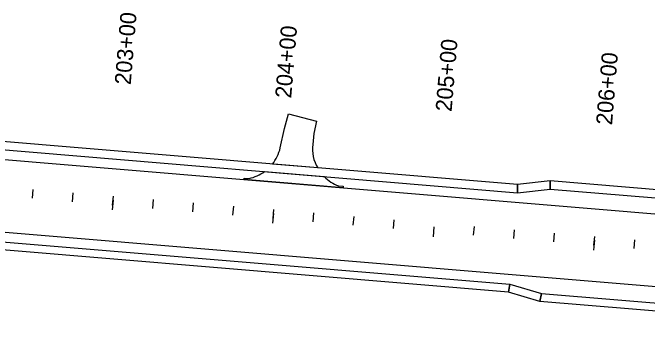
# Model space of a CAD drawing. Extents: x 20499216 to 20505321, y 7953487 to 7960535.
# Drawn here: x 20503938.3 to 20504332.5, y 7953624.2 to 7953822.6 of the extents above; entities that cross this region are included whole.
import ezdxf

# ---------------------------------------------------------------- set-up
doc = ezdxf.new("R2010")
doc.units = 0
for name, color, linetype in [('EXT_CU', 7, 'Continuous'), ('EXT_RR', 7, 'Continuous'), ('NamedBoundary', 7, 'Continuous'), ('Safety', 7, 'Continuous')]:
    doc.layers.add(name, color=color, linetype=linetype)

msp = doc.modelspace()

# ---------------------------------------------------------------- linework, layer by layer
at = {"layer": 'EXT_CU'}
for points in [[(20503897.02, 7953745.48), (20503896.61, 7953740.5), (20504251.88, 7953710.85), (20504251.8, 7953715.88)], [(20504251.88, 7953710.85), (20504272.15, 7953713.17), (20504272.08, 7953718.2), (20504251.8, 7953715.88)], [(20504246.23, 7953649.11), (20503815.16, 7953685.08), (20503815.08, 7953690.11), (20504247.14, 7953654.05)], [(20504265.83, 7953643.46), (20504246.23, 7953649.11), (20504247.14, 7953654.05), (20504266.74, 7953648.4)], [(20504266.74, 7953648.4), (20504496.4, 7953629.24), (20504496.05, 7953624.25), (20504265.83, 7953643.46)]]:
    msp.add_lwpolyline(points, close=True, dxfattribs=at)
msp.add_lwpolyline([(20504432.72, 7953704.8), (20504368.14, 7953710.18), (20504368.14, 7953710.18), (20504272.08, 7953718.2), (20504272.15, 7953713.17), (20504367.73, 7953705.2), (20504367.73, 7953705.2), (20504432.3, 7953699.81)], dxfattribs=at)
at = {"layer": 'EXT_RR'}
for p, q in [((20503950.55, 7953707.4), (20503951, 7953712.84)), ((20503975.46, 7953705.32), (20503975.91, 7953710.76)), ((20504000.63, 7953706.29), (20504000.12, 7953700.19)), ((20504025.29, 7953701.16), (20504025.74, 7953706.6)), ((20504050.2, 7953699.08), (20504050.65, 7953704.52)), ((20504075.11, 7953697), (20504075.57, 7953702.44)), ((20504100.28, 7953697.97), (20504099.77, 7953691.88)), ((20504124.94, 7953692.85), (20504125.39, 7953698.29)), ((20504149.85, 7953690.77), (20504150.31, 7953696.21)), ((20504174.77, 7953688.69), (20504175.22, 7953694.13)), ((20504199.94, 7953689.66), (20504199.43, 7953683.56)), ((20504224.59, 7953684.53), (20504225.05, 7953689.97)), ((20504249.51, 7953682.45), (20504249.96, 7953687.89)), ((20504274.42, 7953680.37), (20504274.88, 7953685.81)), ((20504299.59, 7953681.34), (20504299.08, 7953675.24)), ((20504324.25, 7953676.21), (20504324.7, 7953681.66))]:
    msp.add_line(p, q, dxfattribs=at)
at = {"layer": 'NamedBoundary'}
for p, q in [((20504127.84, 7953726.22), (20504099.61, 7953728.58)), ((20504094.74, 7953723.96), (20504131.87, 7953720.87))]:
    msp.add_line(p, q, dxfattribs=at)
for points in [[(20503281.84, 7953797.82), (20503630.7, 7953768.71), (20503809.08, 7953741.78), (20504366.9, 7953695.23), (20504431.47, 7953689.85)], [(20504104.51, 7953738.74), (20504107.23, 7953750.76), (20504109.62, 7953759.85), (20504126.95, 7953755.29), (20504125.41, 7953747.59), (20504124.76, 7953740.85)], [(20504427.73, 7953645), (20504246.09, 7953660.16), (20503289.01, 7953740.03), (20503289.01, 7953740.03)], [(20504140.67, 7953715.11), (20504143.66, 7953714.87), (20504143.58, 7953713.87), (20504082.04, 7953719), (20504082.12, 7953720), (20504085.11, 7953719.75)]]:
    msp.add_lwpolyline(points, dxfattribs=at)
for centre, radius, start, end in [((20504145.85, 7953737.65), 21.33, 171.3771, 212.4055), ((20504078.51, 7953745.03), 26.76, 322.0441, 346.3982), ((20504080.13, 7953744.25), 25, 281.4903, 305.7659), ((20504149.65, 7953738.45), 25, 224.6943, 248.9699)]:
    msp.add_arc(centre, radius, start, end, dxfattribs=at)
at = {"layer": 'Safety'}
for p, q in [((20504000.37, 7953703.24), (20504000.83, 7953708.68)), ((20504100.03, 7953694.92), (20504100.48, 7953700.37)), ((20504199.94, 7953689.66), (20504199.43, 7953683.56)), ((20504299.33, 7953678.29), (20504299.79, 7953683.73))]:
    msp.add_line(p, q, dxfattribs=at)

# ---------------------------------------------------------------- texts
at = {"layer": 'EXT_RR'}
for s, rotation, p in [('203+00', 85.2296, (20504011.6, 7953777.56)), ('204+00', 85.2296, (20504111.26, 7953769.25)), ('205+00', 85.2296, (20504210.91, 7953760.93)), ('206+00', 85.2308, (20504310.56, 7953752.62))]:
    msp.add_text(s, height=10.02, rotation=rotation, dxfattribs=at).set_placement(p)
at = {"layer": 'Safety'}
msp.add_text('205+00', height=10.02, rotation=85.2296, dxfattribs=at).set_placement((20504210.91, 7953760.93))

doc.saveas('drawing.dxf')
